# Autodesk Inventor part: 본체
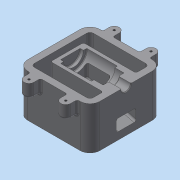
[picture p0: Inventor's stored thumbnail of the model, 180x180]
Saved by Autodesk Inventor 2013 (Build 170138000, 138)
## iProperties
Created: 2018-01
Part Number: 본체
Material: 일반
Document SubType Name: Modeling
Designer: dgall
Density: 1 g/cm^3
Mass: 368.598 g
Surface Area: 834.357 cm^2
Volume: 368.598 cm^3
Author: dgall
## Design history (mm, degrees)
sketch "스케치1"
  geometry: L1 (-55, 55)-(55, 55); L2 (55, 55)-(55, -55); L3 (55, -55)-(-55, -55); L4 (-55, -55)-(-55, 55); L5 (-45, 45)-(45, 45); L6 (45, 45)-(45, -45); L7 (45, -45)-(-45, -45); L8 (-45, -45)-(-45, 45); 5 further points
  constraints: 16 end point, 4 midpoint, 3 parallel, 3 vertical, 2 horizontal, 2 horizontal alignment, 2 vertical alignment
  dimensions: "d0" = 110 distance of L1.start L1.end; "d2" = 110 distance of L1.end L2.end; "d3" = 90 distance of L5.start L5.end; "d4" = 90 distance of L5.end L6.end
extrude "돌출1" new body sketch "스케치1" stored distance "d5" = 65; taper "d6" = 0 deg
fillet "모깎기1" dims "d7" = 15
fillet "모깎기2" dims "d8" = 5
sketch "스케치2"
  geometry: L1 (40, 55)-(-40, 55) reference; L2 (-55, 40)-(-55, -40) reference; L3 (-35.5, 65)-(-35.5, 55); L4 (-20.5, 65)-(-20.5, 55); L5 (20.5, 65)-(20.5, 55); L6 (35.5, 65)-(35.5, 55); A1 r 7.5 centre (-28, 65) between (-20.5, 65) and (-35.5, 65); A2 r 7.5 centre (28, 65) between (35.5, 65) and (20.5, 65); 1 further point
  constraints: 8 end point, 4 point on circle, 4 point on line, 4 vertical, 2 centre point, 2 parallel, 2 tangent, 1 horizontal alignment
  dimensions: "d9" = 7.5 radius of A1; "d10" = 7.5 radius of A2; "d11" = 56 distance of A2.centre A1.centre; "d12" = 27 distance from line of L2 A1.centre; "d13" = 10 distance from line of L1 A1.centre
extrude "돌출2" join sketch "스케치2" distance "d14" = 20; taper "d15" = 0 deg
sketch "스케치3"
  geometry: L1 (-45, 32.5)-(-45, -32.5) reference; L2 (-45, -32.5)-(-55, -32.5) reference; L3 (-55, -32.5)-(-55, 32.5) reference; L4 (-55, 32.5)-(-45, 32.5) reference; L5 (55, -32.5)-(45, -32.5) reference; L6 (45, -32.5)-(45, 32.5) reference; L7 (45, 32.5)-(55, 32.5) reference; L8 (55, 32.5)-(55, -32.5) reference; L9 (-45, -23.936)-(35, -2.5); L10 (35, -2.5)-(35, 32.5); L11 (-45, 32.5)-(-45, -23.936); L12 (-45, 32.5)-(35, 32.5); L13 (40, -32.5)-(-40, -32.5) reference; 1 further point
  constraints: 8 end point, 1 horizontal, 1 point on line, 1 vertical
  dimensions: "d16" = 105 deg angle of L9 L1; "d17" = 30 distance from line of L13 L9.end; "d18" = 80 distance of L1.start L10.end
extrude "돌출3" join sketch "스케치3" stored distance "d19" = 50; taper "d20" = 0 deg
sketch "스케치4"
  geometry: L1 (55, -40)-(55, 40) reference; L2 (75, 0)-(-75, 0); L3 (55, 0)-(55, -7.5); L4 (55, -7.5)-(36, -7.5); L5 (36, -7.5)-(36, -16); L6 (36, -16)-(22, -16); L7 (22, -16)-(22, -20); L8 (22, -20)-(-25, -20); L9 (-25, -20)-(-25, -15); L10 (-25, -15)-(-30, -15); L11 (-30, -15)-(-30, 0); 2 further points
  constraints: 20 end point, 4 vertical, 3 point on line, 2 midpoint, 1 coincident, 1 horizontal
  dimensions: "d21" = 150 distance of L2.start L2.end; "d22" = 19 distance of L3.end L4.end; "d23" = 14 distance of L5.end L6.end; "d24" = 47 distance of L7.end L8.end; "d25" = 5 distance of L9.end L10.end; "d26" = 15 diameter of L4 L2; "d27" = 32 diameter of L6 L2; "d28" = 40 diameter of L8 L2; "d29" = 30 diameter of L10 L2
revolve "회전1" sketch "스케치4" stored, may be unused: angle "d30" = 90 deg
sketch "스케치5"
  geometry: L1 (30, 17.5)-(30, 32.5) reference; L2 (30, 32.5)-(35, 32.5) reference; L3 (35, 32.5)-(35, -2.5) reference; L4 (35, -2.5)-(-45, -23.936) reference; L5 (-45, -23.936)-(-45, -32.5) reference; L6 (-45, -32.5)-(-55, -32.5) reference; L7 (-55, -32.5)-(-55, 25) reference; L8 (-55, 25)-(-36, 25) reference; L9 (-36, 25)-(-36, 16.5) reference; L10 (-36, 16.5)-(-22, 16.5) reference; L11 (-22, 16.5)-(-22, 12.5) reference; L12 (-22, 12.5)-(25, 12.5) reference; L13 (25, 12.5)-(25, 17.5) reference; L14 (25, 17.5)-(30, 17.5) reference; L15 (55, -32.5)-(45, -32.5) reference; L16 (45, -32.5)-(45, 32.5) reference; L17 (45, 32.5)-(55, 32.5) reference; L18 (55, 32.5)-(55, -32.5) reference; L19 (-55, -32.5)-(-55, 32.5) reference; L20 (-55, -3.439)-(-17, 6.743); L21 (-55, -21.439)-(20, -1.343); L22 (20, -1.343)-(20, 28.657); L23 (-17, 6.743)-(-17, 28.657); L24 (-55, -3.439)-(-55, -21.439); L25 (-17, 28.657)-(20, 28.657); 1 further point
  constraints: 12 end point, 2 point on line, 1 horizontal, 1 parallel
  dimensions: "d31" = 75 deg angle of L19 L20; "d32" = 5 distance between parallel lines of L4 L21; "d33" = 18 distance of L21.start L20.start; "d34" = 5 distance between parallel lines of L13 L22; "d35" = 5 distance between parallel lines of L23 L11; "d36" = 30 distance of L21.end L22.end
extrude "돌출4" cut sketch "스케치5" stored distance "d37" = 30; taper "d38" = 0 deg
fillet "모깎기3" dims "d39" = 3
fillet "모깎기4" dims "d40" = 3
sketch "스케치6"
  geometry: L1 (0, 0)-(80, 0) reference; L2 (95, -65)-(95, 0) reference; 2 further points
  constraints: 1 other
  dimensions: "d41" = 20 distance from line of L1 point (40, -20); "d42" = 55 distance from line of L2 point (40, -20)
feature "엠보싱1" sketch "스케치6" dims "d43" = 0.5, "d44" = 0
fillet "모깎기5" dims "d45" = 3
fillet "모깎기6" dims "d46" = 3
fillet "모깎기7" dims "d47" = 3
chamfer "모따기1" distance "d48" = 1; stored, may be unused: second distance "d49" = 2, angle "d50" = 45 deg
fillet "모깎기8" dims "d51" = 1
fillet "모깎기9" dims "d52" = 3
fillet "모깎기10" dims "d53" = 3
hole "구멍1" diameter "d56" = 3.242; stored, may be unused: countersink angle "d60" = 90 deg, drill point angle "d62" = 118 deg; dims "d54" = 10, "d55" = 10, "d57" = 9, "d58" = 4, "d59" = 2, "d61" = 11
node "솔리드1"
mirror "대칭1"
pattern_linear "직사각형 패턴1" dims "d65" = 56
node "절단 모서리 투영1"
node "절단 모서리 투영2"
